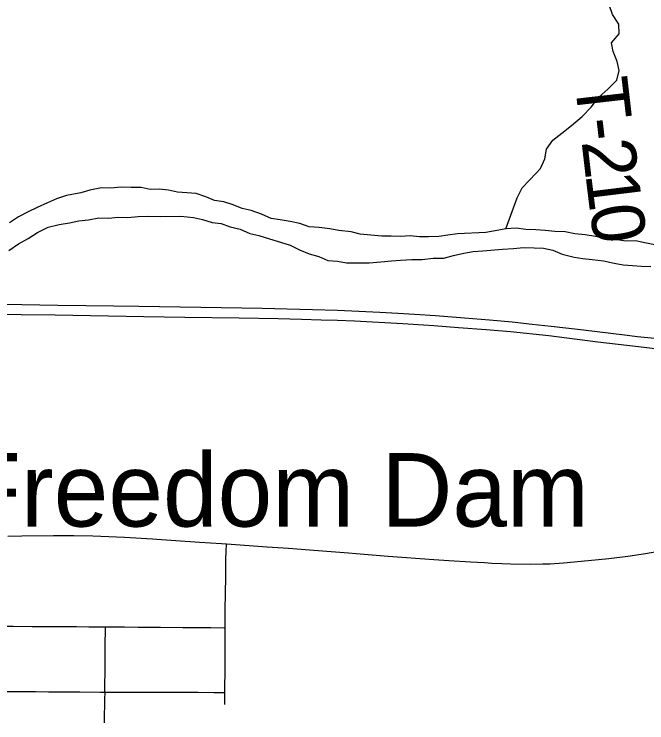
# Model space of a CAD drawing. Extents: x 0 to 34, y 0 to 22.
# Drawn here: x 24.031 to 24.711, y 18.319 to 19.081 of the extents above; entities that cross this region are included whole.
import ezdxf

# ---------------------------------------------------------------- set-up
doc = ezdxf.new("R2010")
doc.units = 0
for name, color, linetype in [('GM_X_Interstate_Route', 7, 'Continuous'), ('GM_X_Major_River', 7, 'Continuous'), ('GM_X_Minor_River', 7, 'Continuous'), ('GM_X_State_Route', 7, 'Continuous'), ('GM_X_Township_Road', 7, 'Continuous'), ('GM_X_Township_Road_Text', 7, 'Continuous'), ('GM_X_Unincorporated_Text', 7, 'Continuous')]:
    doc.layers.add(name, color=color, linetype=linetype)

msp = doc.modelspace()

# ---------------------------------------------------------------- linework, layer by layer
at = {"layer": 'GM_X_Interstate_Route'}
for points in [[(24.01976, 18.7694), (24.07788, 18.76845), (24.13792, 18.76746), (24.16514, 18.76709), (24.23153, 18.76605), (24.29764, 18.76501), (24.35159, 18.76379), (24.37868, 18.76305), (24.40152, 18.76197), (24.4241, 18.76092), (24.44354, 18.75971), (24.46118, 18.75865), (24.48406, 18.75715), (24.51516, 18.75474), (24.54207, 18.75248), (24.56644, 18.75023), (24.58797, 18.74798), (24.60815, 18.74572), (24.64314, 18.74167), (24.68695, 18.73642), (24.70095, 18.73479), (24.71924, 18.73266)], [(23.99038, 18.75888), (24.03863, 18.75832), (24.07493, 18.7579), (24.17041, 18.75624), (24.21428, 18.75549), (24.27278, 18.75462), (24.3148, 18.75392), (24.33985, 18.75324), (24.36103, 18.75261), (24.37867, 18.75209), (24.39666, 18.75136), (24.4486, 18.74848), (24.48222, 18.74644), (24.50857, 18.74428), (24.53819, 18.74205), (24.56458, 18.73985), (24.60559, 18.73563), (24.65837, 18.72905), (24.70224, 18.72398), (24.76361, 18.71623)]]:
    msp.add_lwpolyline(points, dxfattribs=at)
at = {"layer": 'GM_X_Major_River'}
for points in [[(24.24642, 18.88083), (24.23693, 18.88493), (24.22668, 18.88826), (24.21646, 18.88894), (24.20661, 18.88962), (24.19675, 18.89183), (24.1869, 18.89289), (24.17707, 18.89281), (24.16759, 18.89464), (24.15661, 18.89493), (24.14601, 18.89523), (24.13466, 18.89401), (24.12482, 18.89431), (24.11235, 18.89194), (24.10253, 18.88921), (24.08704, 18.88606), (24.07647, 18.88256), (24.06666, 18.87831), (24.05572, 18.8733), (24.04591, 18.86867), (24.03574, 18.86328), (24.02594, 18.85676)], [(24.71952, 18.83323), (24.70891, 18.83543), (24.69905, 18.83763), (24.68808, 18.83716), (24.67747, 18.83898), (24.6661, 18.84003), (24.65587, 18.84223), (24.64488, 18.84404), (24.63351, 18.84509), (24.62328, 18.84729), (24.6123, 18.84758), (24.60169, 18.84864), (24.59185, 18.84933), (24.58087, 18.84962), (24.57064, 18.85106), (24.55967, 18.85022), (24.54795, 18.84823), (24.53812, 18.84626), (24.50748, 18.84489), (24.49727, 18.84367), (24.48744, 18.84208), (24.47647, 18.84162), (24.46662, 18.84192), (24.45677, 18.84298), (24.44656, 18.84215), (24.43634, 18.84245), (24.42612, 18.84237), (24.41438, 18.84342), (24.40302, 18.84447), (24.39315, 18.84705), (24.3799, 18.84847), (24.37042, 18.85029), (24.35868, 18.85172), (24.34807, 18.8524), (24.3382, 18.85611), (24.32759, 18.85831), (24.31698, 18.86012), (24.30713, 18.86157), (24.29687, 18.86604), (24.28586, 18.87013), (24.27601, 18.87233), (24.26652, 18.87605), (24.25627, 18.87938), (24.24642, 18.88083)], [(24.02536, 18.8269), (24.0355, 18.83424), (24.04604, 18.84006), (24.0562, 18.84625), (24.0675, 18.85208), (24.07921, 18.85487), (24.09055, 18.85691), (24.10037, 18.85892), (24.11097, 18.86018), (24.12193, 18.86221), (24.13253, 18.86196), (24.14275, 18.86283), (24.15298, 18.86258), (24.16433, 18.86347), (24.17569, 18.86398), (24.18781, 18.86374), (24.21015, 18.864), (24.2238, 18.86264), (24.23329, 18.86047), (24.24394, 18.85718), (24.25342, 18.85615), (24.26331, 18.85247), (24.27394, 18.84994), (24.28422, 18.8455), (24.29409, 18.84333), (24.30549, 18.83967), (24.31727, 18.83601), (24.32753, 18.83271), (24.33781, 18.8279), (24.34809, 18.82346), (24.35835, 18.82054), (24.36824, 18.81648), (24.37848, 18.81546), (24.38835, 18.81367), (24.41258, 18.81396), (24.42507, 18.81486), (24.43642, 18.81614), (24.44626, 18.81663), (24.45837, 18.81753), (24.46973, 18.81728), (24.48146, 18.81894), (24.49282, 18.81869), (24.50339, 18.82185), (24.51435, 18.82426), (24.52456, 18.8259), (24.53477, 18.82678), (24.55597, 18.82854), (24.5677, 18.82906), (24.57867, 18.83033), (24.59003, 18.83008), (24.59989, 18.82944), (24.61014, 18.82728), (24.62003, 18.82322), (24.63295, 18.81995), (24.64243, 18.81854), (24.65229, 18.81752), (24.66442, 18.81614), (24.67581, 18.81361), (24.68568, 18.81183), (24.69554, 18.8108), (24.70539, 18.81016), (24.71525, 18.8099)]]:
    msp.add_lwpolyline(points, dxfattribs=at)
at = {"layer": 'GM_X_Minor_River'}
for points in [[(24.59209, 18.91033), (24.59687, 18.91536), (24.60137, 18.92562), (24.60322, 18.93588), (24.61, 18.94578), (24.61982, 18.95304), (24.63001, 18.96144), (24.64172, 18.97098), (24.65115, 18.98127), (24.65943, 18.99194), (24.66925, 19.00034), (24.67868, 19.01025), (24.68129, 19.02051), (24.67935, 19.03037), (24.67475, 19.04097), (24.67319, 19.05045), (24.68148, 19.05997), (24.68105, 19.07022), (24.67418, 19.08081), (24.67072, 19.09104)], [(24.55962, 18.85021), (24.57152, 18.88369), (24.57717, 18.89455), (24.59209, 18.91033)]]:
    msp.add_lwpolyline(points, dxfattribs=at)
at = {"layer": 'GM_X_State_Route'}
for points in [[(24.39854, 18.50129), (24.43284, 18.49839), (24.48204, 18.49478), (24.49807, 18.49378), (24.52156, 18.49242), (24.53645, 18.49161), (24.54451, 18.4911), (24.55505, 18.49066), (24.56436, 18.49041), (24.5861, 18.49005), (24.59912, 18.49014), (24.60716, 18.49042), (24.62139, 18.49136), (24.64797, 18.49374), (24.67021, 18.49592), (24.69052, 18.49854), (24.70955, 18.50148), (24.74815, 18.50804), (24.79592, 18.5163), (24.86532, 18.52858)], [(24.02413, 18.52007), (24.03905, 18.5204), (24.07325, 18.52078), (24.07884, 18.52074), (24.095, 18.52075), (24.11552, 18.52044), (24.12423, 18.52015), (24.14972, 18.51902), (24.17951, 18.51718)], [(24.17951, 18.51718), (24.18448, 18.51687), (24.23034, 18.51364), (24.2539, 18.51204), (24.25921, 18.51166)], [(24.25921, 18.51166), (24.30286, 18.5085), (24.32589, 18.50695), (24.34859, 18.50533), (24.39047, 18.50198), (24.39854, 18.50129)]]:
    msp.add_lwpolyline(points, dxfattribs=at)
at = {"layer": 'GM_X_Township_Road'}
for points in [[(24.25777, 18.42154), (24.25783, 18.44397), (24.25802, 18.45531), (24.25834, 18.47988), (24.25849, 18.4915), (24.25862, 18.49737), (24.2587, 18.50143), (24.25891, 18.50559), (24.25908, 18.50918), (24.25921, 18.51166)], [(23.98712, 18.42339), (23.99404, 18.42335), (24.00977, 18.42326), (24.03002, 18.42315), (24.05017, 18.42302), (24.07526, 18.42286), (24.098, 18.42272), (24.11127, 18.42263), (24.12511, 18.42251), (24.12932, 18.42248)], [(24.12846, 18.3524), (24.12853, 18.36223), (24.12861, 18.37245), (24.12866, 18.38401), (24.12872, 18.39624), (24.12883, 18.40242), (24.12895, 18.40675), (24.12918, 18.41652), (24.1293, 18.42134), (24.12932, 18.42248)], [(24.12932, 18.42248), (24.13542, 18.42245), (24.14954, 18.42239), (24.16416, 18.42226), (24.18837, 18.42205), (24.21215, 18.42187), (24.24226, 18.42165), (24.2566, 18.42154), (24.25777, 18.42154)], [(24.2575, 18.35203), (24.25757, 18.36042), (24.25761, 18.37148), (24.25767, 18.38736), (24.25774, 18.41373), (24.25777, 18.42154)], [(23.98672, 18.35334), (23.99478, 18.35328), (24.01735, 18.35312), (24.03543, 18.35298), (24.05399, 18.35284), (24.06785, 18.35279), (24.08353, 18.35274), (24.10152, 18.3526), (24.12362, 18.35243), (24.12846, 18.3524)], [(24.12799, 18.31934), (24.12812, 18.32653), (24.12835, 18.33931), (24.12841, 18.34598), (24.12882, 18.35099), (24.12846, 18.3524)], [(24.12846, 18.3524), (24.13353, 18.35238), (24.14054, 18.35236), (24.15341, 18.35234), (24.16843, 18.35231), (24.18856, 18.35227), (24.20473, 18.35222), (24.22858, 18.35214), (24.24574, 18.35207), (24.25631, 18.35204), (24.2575, 18.35203)], [(24.2573, 18.33915), (24.25747, 18.34908), (24.2575, 18.35203)]]:
    msp.add_lwpolyline(points, dxfattribs=at)

# ---------------------------------------------------------------- texts
at = {"layer": 'GM_X_Township_Road_Text'}
for s, rotation, p in [('T', 276.55837, (24.63333, 19.00987)), ('-', 276.5622, (24.63818, 18.96764)), ('2', 276.66483, (24.64086, 18.94435)), ('1', 276.98174, (24.64497, 18.90925)), ('0', 277.93661, (24.64935, 18.87348))]:
    msp.add_text(s, height=0.05682, rotation=rotation, dxfattribs=at).set_placement(p)
at = {"layer": 'GM_X_Unincorporated_Text'}
msp.add_text('Freedom Dam', height=0.0789773, rotation=0.00001, dxfattribs=at).set_placement((23.9738, 18.53031))

doc.saveas('drawing.dxf')
